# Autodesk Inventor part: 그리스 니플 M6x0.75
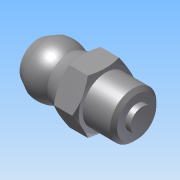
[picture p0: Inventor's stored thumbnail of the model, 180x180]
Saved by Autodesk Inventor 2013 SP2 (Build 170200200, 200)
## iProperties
Created: 2025-10
Part Number: 그리스 니플 M6x0.75
Material: Generic
Document SubType Name: Modeling
Designer: 601
Density: 1 g/cm^3
변환 표준: STEP AP214IS
전처리기: Build: 200, Release: 2013 SP2 Update 6 - Date: Thu 07/17/2014
전송 단위: 밀리미터
불확실성: 0.01
Author: 601
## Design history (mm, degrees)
node "그리스 니플 M6x0.751"
body "Solid1"
node "기준1"
